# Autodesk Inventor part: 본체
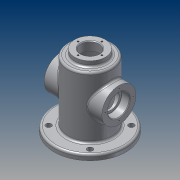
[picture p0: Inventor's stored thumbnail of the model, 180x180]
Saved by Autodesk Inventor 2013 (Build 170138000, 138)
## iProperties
Created: 2014-12
Part Number: 본체
Material: 알루미늄 6061
Document SubType Name: Modeling
Designer: SD
Density: 2.71 g/cm^3
Mass: 479.565 g
Surface Area: 607.361 cm^2
Volume: 176.961 cm^3
Author: SD
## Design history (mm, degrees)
sketch "스케치1"
  geometry: C1 r 32.5 at (0, 0); C2 r 52.5 at (0, 0); 1 further point
  constraints: 2 centre point, 2 coincident
  dimensions: "d0" = 65 diameter of C1; "d1" = 105 diameter of C2
extrude "돌출1" new body sketch "스케치1" distance "d3" = 98; taper "d4" = 0 deg
fillet "모깎기1" dims "d5" = 3
feature "쉘1" dims "d6" = 5
extrude "돌출2" join sketch "스케치1" distance "d7" = 8; taper "d8" = 0 deg
sketch "스케치2"
  geometry: C1 r 22.5 at (0, 0); 1 further point
  constraints: 1 centre point, 1 coincident
  dimensions: "d9" = 45 diameter of C1
extrude "돌출3" join sketch "스케치2" distance "d10" = 8; taper "d11" = 0 deg
node "작업 평면1"
node "작업 평면2"
sketch "스케치5"
  geometry: L1 (-52.5, 0)-(52.5, 0) reference; C1 r 25 at (0, 55); 1 further point
  constraints: 1 centre point, 1 vertical alignment
  dimensions: "d14" = 50 diameter of C1; "d15" = 55 distance from line of L1 C1.centre
extrude "돌출4" join sketch "스케치5" stored distance "d16" = 8; taper "d17" = 0 deg
hole "구멍1" diameter "d20" = 25; stored, may be unused: countersink angle "d24" = 90 deg, drill point angle "d26" = 0 deg; dims "d18" = 10, "d19" = 10, "d21" = 6, "d22" = 32, "d23" = 12, "d25" = 42.5
sketch "스케치6"
  geometry: C1 r 25 at (0, 0) reference; 2 further points
  constraints: 1 horizontal alignment
  dimensions: "d28" = 20.5 distance of point (-20.5, 0) C1.centre
hole "구멍2" sketch "스케치6" at (-20.5, 0) diameter "d29" = 2.459; stored, may be unused: countersink angle "d33" = 90 deg, drill point angle "d35" = 118 deg; dims "d30" = 6, "d31" = 32, "d32" = 12, "d34" = 8
fillet "모깎기3" dims "d39" = 0.3
chamfer "모따기1" distance "d40" = 1; stored, may be unused: second distance "d41" = 2, angle "d42" = 45 deg
hole "구멍3" diameter "d45" = 27; stored, may be unused: countersink angle "d49" = 90 deg, drill point angle "d51" = 118 deg; dims "d43" = 10, "d44" = 10, "d46" = 6, "d47" = 4, "d48" = 2, "d50" = 8
sketch "스케치7"
  geometry: 2 further points
  constraints: 1 vertical alignment
  dimensions: "d52" = 17.5 distance of point (0, 0) point (0, 17.5)
hole "구멍4" sketch "스케치7" at (0, 17.5) diameter "d53" = 2.459; stored, may be unused: countersink angle "d57" = 90 deg, drill point angle "d59" = 118 deg; dims "d54" = 6, "d55" = 4, "d56" = 2, "d58" = 8
chamfer "모따기2" distance "d63" = 1; stored, may be unused: second distance "d64" = 2, angle "d65" = 45 deg
sketch "스케치8" dims "d67" = 86
  geometry: L1 (0, 0)-(30.406, 30.406); L2 (0, 0)-(43, 0); C1 r 4 at (30.406, 30.406); 1 further point
  constraints: 4 end point, 2 coincident, 1 centre point, 1 equal length, 1 horizontal, 3 other
  dimensions: "d68" = 45 deg angle of L2 L1; "d69" = 8 diameter of C1
extrude "돌출5" cut sketch "스케치8" stored distance "d70" = 10; taper "d71" = 0 deg
node "작업 평면3"
sketch "스케치9"
  geometry: L1 (-29.5, 98)-(29.5, 98) reference; 2 further points
  constraints: 1 vertical alignment, 1 other
  dimensions: "d75" = 9 distance from line of L1 point (0, 89)
feature "엠보싱1" sketch "스케치9" dims "d14" = 50, "d76" = 1, "d77" = 0
fillet "모깎기4" dims "d78" = 3
fillet "모깎기5" dims "d79" = 3
node "솔리드1"
pattern_circular "원형 패턴1" dims angle "d37" = 360 deg
mirror "대칭1"
pattern_circular "원형 패턴2" dims angle "d61" = 360 deg
pattern_circular "원형 패턴3" dims angle "d73" = 360 deg
node "투영된 루프1"
other parameters: "d12" = 55, "d13" = 42.5
